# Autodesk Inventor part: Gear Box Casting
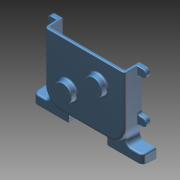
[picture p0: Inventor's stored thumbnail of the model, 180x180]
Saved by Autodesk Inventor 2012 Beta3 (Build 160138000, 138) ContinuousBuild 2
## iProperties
Created: 2008-05
Part Number: Gear Box Casting
Material: Aluminum-6061
Document SubType Name: Modeling
Designer: Thom Tremblay
Mass: 2781.62 g
Surface Area: 1986.38 cm^2
Volume: 1026.43 cm^3
Density: 2.71 g/cm^3
Author: Thom Tremblay
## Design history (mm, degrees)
sketch "Sketch1"
  geometry: L1 (-127, 208.28)-(0, 208.28); L2 (127, 208.28)-(127, 0); L3 (0, 0)-(-127, 0); L4 (-127, 0)-(-127, 208.28); L5 (0, 0)-(0, 208.28); L6 (0, 208.28)-(127, 208.28); L7 (0, 0)-(127, 0); 1 further point
  constraints: 14 end point, 3 parallel, 2 perpendicular, 1 coincident, 1 horizontal
  dimensions: "d0" = 254 distance of L1.start L2.start; "d1" = 208.28 distance of L3.end L1.start
extrude "Extrusion1" new body sketch "Sketch1" distance "d2" = 50.8; taper "d3" = 0 deg
feature "FaceDraft1" dims angle "d60" = 2 deg
fillet "Fillet1" dims "d10" = 50.8
fillet "Fillet2" dims "d11" = 10.16
shell "Shell1" dims "d12" = 7.62
sketch "Sketch3"
  geometry: L1 (58.42, 3.81)-(58.42, -27.94); L2 (58.42, -27.94)-(172.72, -27.94); L3 (172.72, -27.94)-(172.72, 3.81); L4 (172.72, 3.81)-(58.42, 3.81); L5 (127, 50.769)-(127, 208.28) reference; L6 (0, 0)-(76.231, 0) reference; 1 further point
  constraints: 8 end point, 2 parallel, 1 perpendicular, 1 vertical
  dimensions: "d13" = 31.75 distance of L2.end L3.end; "d14" = 45.72 distance between parallel lines of L5 L3; "d15" = 27.94 distance between parallel lines of L6 L2; "d16" = 114.3 distance of L1.end L2.end
extrude "Extrusion3" join sketch "Sketch3" distance "d17" = 40.64; taper "d18" = -2 deg
fillet "Fillet16" dims "d61" = 17.78
fillet "Fillet26" dims "d73" = 15.24
sketch "Sketch5"
  geometry: L1 (127, 50.769)-(127, 208.28) reference; L2 (127, 208.28)-(119.375, 208.28) reference; L3 (0, 0)-(58.42, 0) reference; L4 (58.42, 0)-(58.42, -27.94) reference; L5 (127, 208.28)-(142.24, 208.28); L6 (142.24, 182.88)-(127, 182.88); L7 (30.48, 0)-(30.48, -10.16); L8 (43.18, -22.86)-(58.42, -22.86); L9 (127, 50.769)-(142.24, 50.769); L10 (142.24, 76.169)-(127, 76.169); A1 r 12.7 centre (142.24, 195.58) between (142.24, 182.88) and (142.24, 208.28); A2 r 12.7 centre (43.18, -10.16) between (30.48, -10.16) and (43.18, -22.86); A3 r 12.7 centre (142.24, 63.469) between (142.24, 50.769) and (142.24, 76.169); 4 further points; 1 other entity
  constraints: 12 end point, 6 point on circle, 6 tangent, 5 perpendicular, 4 point on line, 3 centre point, 2 parallel, 1 equal radius, 1 other
  dimensions: "d34" = 12.7 radius of A1; "d35" = 15.24 distance of L1.end L5.end; "d37" = 12.7 radius of A2; "d38" = 15.24 distance of L8.start L8.end; "d59" = 10.16 distance of L7.start L7.end
extrude "Extrusion5" join sketch "Sketch5" distance "d40" = 12.7; taper "d41" = -2 deg
extrude "Extrusion7" join sketch "Sketch5" stored distance "d47" = 12.7; taper "d48" = -2 deg
extrude "Extrusion8" join sketch "Sketch5" stored distance "d50" = 12.7; taper "d51" = -2 deg
fillet "Fillet17" dims "d62" = 7.62
fillet "Fillet18" dims "d64" = 2.54
fillet "Fillet19" dims "d65" = 2.54
fillet "Fillet22" dims "d68" = 2.54
fillet "Fillet25" dims "d71" = 2.54
fillet "Fillet27" dims "d74" = 5.08
fillet "Fillet31" dims "d78" = 2.54
fillet "Fillet32" dims "d79" = 2.54
mirror "Mirror3"
sketch "Sketch4"
  geometry: L1 (-127, 50.769)-(-127, 182.88) reference; L2 (-142.24, 208.28)-(-119.375, 208.28) reference; L3 (-50.8, 73.66)-(44.238, 137.16); C1 r 27.94 at (-50.8, 73.66); C2 r 27.94 at (44.238, 137.16); 1 further point
  constraints: 2 centre point, 2 end point, 1 equal radius
  dimensions: "d22" = 95.0381 horizontal distance of L3.end L3.start (derived); "d23" = 76.2 distance from line of L1 L3.start; "d24" = 63.5 vertical distance of L3.end L3.start; "d27" = 55.88 diameter of C2; "d72" = 134.62 distance from line of L2 L3.start; "d80" = 114.3 distance of L3.start L3.end
extrude "Extrusion4" join sketch "Sketch4" distance "d28" = 17.78; taper "d29" = -2 deg
fillet "Fillet5" dims "d30" = 2.54, "d31" = 5.08
workplane "Work Plane2"
sketch "Sketch7"
  geometry: L1 (0, 0)-(0.906, 25.948) reference; L2 (107.89, 38.212)-(109.223, 0) reference; L3 (100.134, 5.546)-(99.441, 25.4); L4 (99.441, 25.4)-(39.287, 25.4); L5 (29.635, 15.748)-(29.635, 1.955); A1 r 9.652 centre (39.287, 15.748) between (39.287, 25.4) and (29.635, 15.748); 3 further points; 1 other entity
  constraints: 6 end point, 2 point on circle, 2 tangent, 1 centre point, 1 horizontal, 1 parallel, 1 other
  dimensions: "d91" = 9.652 radius of A1; "d92" = 8.89 distance between parallel lines of L2 L3; "d93" = 2 deg angle of L5 L1; "d94" = 25.4 distance from line of L2.end L4
extrude "Extrusion9" cut sketch "Sketch7" distance "d96" = 15.875; taper "d97" = -2 deg
mirror "Mirror4"
fillet "Fillet35" dims "d100" = 6.35, "d101" = 2.54
sketch "Rib Sketch"
  geometry: L1 (-21.093, 93.509)-(15.839, 118.185); C1 r 27.405 at (-50.8, 73.66) reference; C2 r 27.405 at (44.238, 137.16) reference; 1 further point
  constraints: 2 end point, 2 point on line
feature "Rib1" sketch "Rib Sketch" dims "d82" = 7.62, "d83" = 2.54, "d84" = 5 deg, "d85" = 0, "d86" = 2.54, "d87" = 2.54
fillet "Fillet33" dims "d88" = 3.048
body "Solid1"
other parameters: "d42" = 7.62, "d46" = 12.7, "d49" = 12.7, "d81" = 10.16, "d95" = 15.875
